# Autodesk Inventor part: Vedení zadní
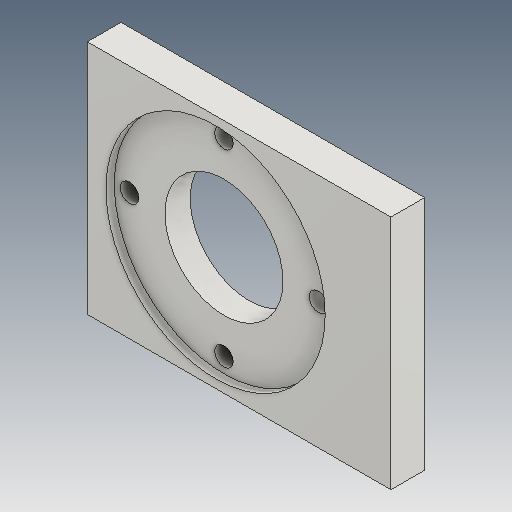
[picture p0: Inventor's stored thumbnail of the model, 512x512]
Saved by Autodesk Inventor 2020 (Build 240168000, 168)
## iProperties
Created: 2025-03
Part Number: Vedení zadní
Material: Ocel
Document SubType Name: Modeling
Designer: doma
Density: 7.85 g/cm^3
Appearance: Ocel
Mass: 2937.51 g
Surface Area: 621.57 cm^2
Volume: 374.205 cm^3
Author: doma
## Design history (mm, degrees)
sketch "Náčrt1"
  geometry: L1 (1063.55, 267.515)-(1243.55, 267.515); L2 (1243.55, 267.515)-(1243.55, 407.515); L3 (1243.55, 407.515)-(1063.55, 407.515); L4 (1063.55, 407.515)-(1063.55, 267.515); C1 r 35 at (1139.55, 337.515); 4 further points
  constraints: 8 end point, 1 centre point
extrude "Vysunutí1" new body sketch "Náčrt1" distance "d54" = 20; taper "d55" = 0 deg
sketch "Náčrt2"
  geometry: C1 r 35 at (1139.55, 337.515) reference; C2 r 65 at (1139.55, 337.515); 1 further point
  constraints: 1 centre point, 1 coincident
  dimensions: "d56" = 130 diameter of C2
extrude "Vysunutí2" cut sketch "Náčrt2" distance "d57" = 5; taper "d58" = 0 deg
sketch "Náčrt3"
  geometry: C1 r 5.5 at (0, 56) reference; C2 r 5.5 at (-56, 0) reference; C3 r 5.5 at (56, 0) reference; C4 r 5.5 at (0, -56) reference; 1 further point
extrude "Vysunutí3" cut sketch "Náčrt3" extent not by distance; stored distance "d59" = 5; taper "d60" = 0 deg
node "Těleso1"
node "Referenční1"
node "Referenční2"
node "Referenční3"
node "Referenční4"
